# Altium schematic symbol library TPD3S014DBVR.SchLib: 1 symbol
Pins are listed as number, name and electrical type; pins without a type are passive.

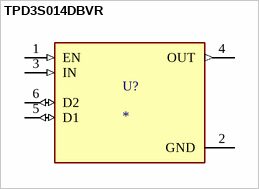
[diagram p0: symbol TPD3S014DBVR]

## TPD3S014DBVR
designator U?
Current-limit switch and D+/D ESD protection for USB Host ports 6-SOT-23 -40 to 85; MP: TPD3S014DBVR; MF: Texas Instruments
footprint TPD3S014DBVR
pins: 1 EN (in), 2 GND (power), 3 IN (in), 4 OUT (out), 5 D1 (io), 6 D2 (io)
